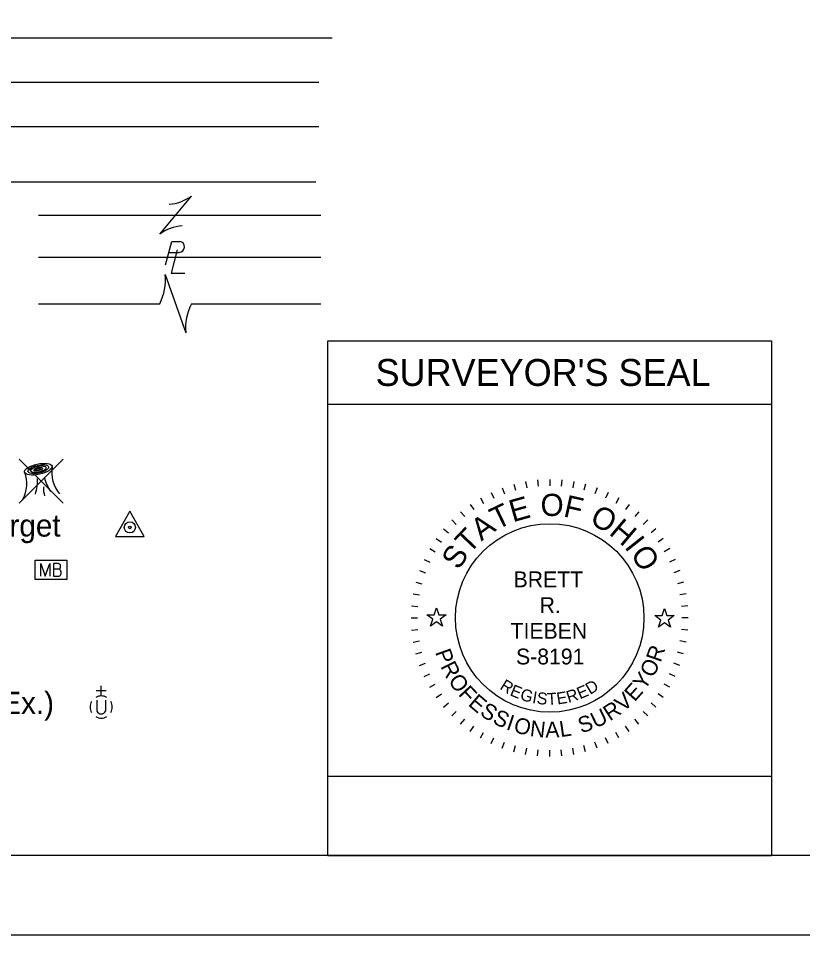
# Model space of a CAD drawing. Extents: x 0 to 34, y 0 to 22.
# Drawn here: x 12.19 to 17.15, y 0 to 5.79 of the extents above; entities that cross this region are included whole.
import ezdxf

# ---------------------------------------------------------------- set-up
doc = ezdxf.new("R2010")
doc.units = 0
for name, color, linetype in [('SH_Border', 7, 'Continuous'), ('SH_Cut_Line', 7, 'Continuous'), ('SH_Data', 7, 'Continuous'), ('SH_Text', 7, 'Continuous')]:
    doc.layers.add(name, color=color, linetype=linetype)

msp = doc.modelspace()

# ---------------------------------------------------------------- linework, layer by layer
at = {"layer": 'SH_Border'}
msp.add_lwpolyline([(1.5, 21.5), (33.5, 21.5), (33.5, 0.5), (1.5, 0.5)], close=True, dxfattribs=at)
at = {"layer": 'SH_Cut_Line'}
msp.add_lwpolyline([(0, 0), (34, 0), (34, 22), (0, 22)], close=True, dxfattribs=at)
at = {"layer": 'SH_Data'}
for p, q in [((14.1482, 0.5), (14.1482, 3.75)), ((14.1482, 3.75), (16.9482, 3.75)), ((16.9482, 3.75), (16.9482, 0.5)), ((14.1482, 3.35), (16.9482, 3.35)), ((15.3217, 2.8452), (15.3321, 2.8065)), ((15.3962, 2.8617), (15.4032, 2.8223)), ((15.4719, 2.8717), (15.4754, 2.8318)), ((15.5482, 2.875), (15.5482, 2.835)), ((15.6244, 2.8717), (15.6209, 2.8318)), ((15.7001, 2.8617), (15.6932, 2.8223)), ((15.7746, 2.8452), (15.7643, 2.8065)), ((15.1784, 2.793), (15.1953, 2.7568)), ((15.2489, 2.8222), (15.2626, 2.7846)), ((15.8474, 2.8222), (15.8338, 2.7846)), ((15.918, 2.793), (15.9011, 2.7568)), ((15.1107, 2.7578), (15.1307, 2.7231)), ((15.9857, 2.7578), (15.9657, 2.7231)), ((14.9857, 2.6703), (15.0114, 2.6396)), ((15.0463, 2.7168), (15.0692, 2.684)), ((16.05, 2.7168), (16.0271, 2.684)), ((16.1106, 2.6703), (16.0849, 2.6396)), ((14.9294, 2.6187), (14.9577, 2.5904)), ((16.1669, 2.6187), (16.1386, 2.5904)), ((14.8779, 2.5624), (14.9085, 2.5367)), ((16.2185, 2.5624), (16.1878, 2.5367)), ((14.8314, 2.5019), (14.8642, 2.4789)), ((16.2649, 2.5019), (16.2322, 2.4789)), ((14.7904, 2.4375), (14.825, 2.4175)), ((16.3059, 2.4375), (16.2713, 2.4175)), ((14.7551, 2.3698), (14.7914, 2.3529)), ((16.3412, 2.3698), (16.3049, 2.3529)), ((14.7259, 2.2993), (14.7635, 2.2856)), ((16.3704, 2.2993), (16.3328, 2.2856)), ((14.703, 2.2265), (14.7416, 2.2161)), ((16.3933, 2.2265), (16.3547, 2.2161)), ((14.6865, 2.1519), (14.7258, 2.145)), ((16.4099, 2.1519), (16.3705, 2.145)), ((14.6765, 2.0763), (14.7163, 2.0728)), ((16.4198, 2.0763), (16.38, 2.0728)), ((14.6732, 2), (14.7132, 2)), ((16.4232, 2), (16.3832, 2)), ((14.6765, 1.9237), (14.7163, 1.9272)), ((16.4198, 1.9237), (16.38, 1.9272)), ((14.6865, 1.8481), (14.7258, 1.855)), ((16.4099, 1.8481), (16.3705, 1.855)), ((14.703, 1.7735), (14.7416, 1.7839)), ((16.3933, 1.7735), (16.3547, 1.7839)), ((14.7259, 1.7007), (14.7635, 1.7144)), ((16.3704, 1.7007), (16.3328, 1.7144)), ((14.7551, 1.6302), (14.7914, 1.6471)), ((16.3412, 1.6302), (16.3049, 1.6471)), ((14.7904, 1.5625), (14.825, 1.5825)), ((16.3059, 1.5625), (16.2713, 1.5825)), ((14.8314, 1.4981), (14.8642, 1.5211)), ((16.2649, 1.4981), (16.2322, 1.5211)), ((14.8779, 1.4376), (14.9085, 1.4633)), ((16.2185, 1.4376), (16.1878, 1.4633)), ((14.9294, 1.3813), (14.9577, 1.4096)), ((16.1669, 1.3813), (16.1386, 1.4096)), ((14.9857, 1.3297), (15.0114, 1.3604)), ((16.1106, 1.3297), (16.0849, 1.3604)), ((15.0463, 1.2832), (15.0692, 1.316)), ((15.1107, 1.2422), (15.1307, 1.2769)), ((15.9857, 1.2422), (15.9657, 1.2769)), ((16.05, 1.2832), (16.0271, 1.316)), ((15.1784, 1.207), (15.1953, 1.2432)), ((15.2489, 1.1778), (15.2626, 1.2154)), ((15.8474, 1.1778), (15.8338, 1.2154)), ((15.918, 1.207), (15.9011, 1.2432)), ((15.3217, 1.1548), (15.3321, 1.1935)), ((15.3962, 1.1383), (15.4032, 1.1777)), ((15.4719, 1.1283), (15.4754, 1.1682)), ((15.5482, 1.125), (15.5482, 1.165)), ((15.6244, 1.1283), (15.6209, 1.1682)), ((15.7001, 1.1383), (15.6932, 1.1777)), ((15.7746, 1.1548), (15.7643, 1.1935)), ((14.1482, 0.5), (16.9482, 0.5))]:
    msp.add_line(p, q, dxfattribs=at)
for points in [[(14.7718, 2.02), (14.8187, 2.02), (14.8332, 2.0645), (14.8477, 2.02), (14.8945, 2.02), (14.8567, 1.9924), (14.8711, 1.9478), (14.8332, 1.9754), (14.7952, 1.9478), (14.8097, 1.9924)], [(16.2109, 2.0146), (16.2578, 2.0146), (16.2723, 2.0591), (16.2868, 2.0146), (16.3336, 2.0146), (16.2958, 1.987), (16.3103, 1.9424), (16.2723, 1.97), (16.2343, 1.9424), (16.2488, 1.987)], [(14.1482, 0.5), (14.1482, 1), (16.9482, 1), (16.9482, 0.5)]]:
    msp.add_lwpolyline(points, close=True, dxfattribs=at)
msp.add_circle((15.5482, 2), 0.595, dxfattribs=at)
at = {"layer": 'SH_Text'}
for p, q in [((10.6907, 5.6637), (14.1741, 5.6637)), ((10.1904, 5.3837), (14.0904, 5.3837)), ((10.1904, 5.1037), (14.0904, 5.1037)), ((9.7227, 4.7537), (14.0727, 4.7537)), ((13.0859, 4.4237), (13.2859, 4.6637)), ((12.3204, 4.5437), (14.1027, 4.5437)), ((13.1859, 4.5437), (13.1859, 4.5437)), ((13.1436, 4.3087), (13.2084, 4.3087)), ((12.3204, 4.2791), (14.1027, 4.2791)), ((13.1837, 4.2775), (13.1837, 4.2775)), ((13.1209, 4.1679), (13.2509, 3.7997)), ((12.3204, 3.9837), (13.086, 3.9837)), ((13.1859, 3.9838), (13.1859, 3.9838)), ((13.2858, 3.9837), (14.1027, 3.9837)), ((12.1991, 3.0028), (12.4772, 2.7247)), ((12.4772, 3.0028), (12.1991, 2.7247)), ((12.3382, 2.8638), (12.3382, 2.8638)), ((12.3382, 2.8637), (12.3382, 2.8637)), ((12.3994, 2.3037), (12.3994, 2.3037)), ((12.7168, 1.5074), (12.7168, 1.5709)), ((12.7485, 1.5391), (12.6849, 1.5391)), ((12.6896, 1.4804), (12.6896, 1.4115)), ((12.7439, 1.4804), (12.7439, 1.4115)), ((12.7168, 1.4374), (12.7168, 1.4374))]:
    msp.add_line(p, q, dxfattribs=at)
for points in [[(13.1226, 4.2291), (13.1617, 4.3773), (13.2134, 4.3772)], [(13.197, 4.3255), (13.1574, 4.1777), (13.2448, 4.1777)], [(12.3346, 2.2637), (12.3346, 2.3437), (12.3636, 2.2637), (12.3913, 2.3437), (12.3913, 2.2637)], [(12.4505, 2.3072), (12.4537, 2.3104), (12.4556, 2.3123), (12.4568, 2.3141), (12.4575, 2.3154), (12.4587, 2.3179), (12.4594, 2.3198), (12.4606, 2.3242), (12.4606, 2.3261), (12.4606, 2.3286), (12.46, 2.3324), (12.4587, 2.3356), (12.4568, 2.3381), (12.4537, 2.3406), (12.4512, 2.3419), (12.4499, 2.3425), (12.4468, 2.3437), (12.4159, 2.3437), (12.4159, 2.2637), (12.4505, 2.2637), (12.4549, 2.2663), (12.4587, 2.2694), (12.4619, 2.2745), (12.4638, 2.2801), (12.4644, 2.2858), (12.4644, 2.2896), (12.4631, 2.2934), (12.4606, 2.299), (12.4575, 2.3028), (12.4505, 2.3072), (12.4159, 2.3072)]]:
    msp.add_lwpolyline(points, dxfattribs=at)
for points in [[(12.8076, 2.5137), (12.9876, 2.5137), (12.8976, 2.6747)], [(12.2994, 2.3648), (12.4994, 2.3648), (12.4994, 2.2427), (12.2994, 2.2427)]]:
    msp.add_lwpolyline(points, close=True, dxfattribs=at)
for radius in [0.035, 0.008]:
    msp.add_circle((12.8976, 2.5716), radius, dxfattribs=at)
for centre, radius, start, end in [((13.1278, 4.8787), 0.2668, 273.69448, 306.33701), ((13.244, 4.2088), 0.2668, 93.69448, 126.33701), ((13.2082, 4.3431), 0.0345, 270.47098, 81.3281), ((12.7889, 4.1355), 0.3335, 332.94224, 5.58476), ((13.5829, 3.8321), 0.3335, 152.94224, 185.58476), ((12.6185, 2.9208), 0.2146, 171.41061, 219.91939), ((12.0466, 2.8464), 0.2001, 331.53375, 20.92689), ((12.0623, 2.865), 0.2527, 340.79377, 3.54808), ((12.6636, 2.9666), 0.316, 194.9653, 212.12159), ((12.5334, 2.8237), 0.1819, 178.79264, 197.12241), ((12.7168, 1.4374), 0.07, 60.01836, 120.01574), ((12.7168, 1.4374), 0.07, 150.01836, 209.98164), ((12.7168, 1.4374), 0.07, 330.01836, 29.98164), ((12.7167, 1.4243), 0.03, 205.19243, 334.80757), ((12.7168, 1.4374), 0.07, 239.98426, 299.98164)]:
    msp.add_arc(centre, radius, start, end, dxfattribs=at)
for major_axis in [(0.0868, 0.0187), (0.0651, 0.0141), (0.0488, 0.0105), (0.0275, 0.0059), (0.0154, 0.0033)]:
    msp.add_ellipse((12.3194, 2.9393), major_axis=major_axis, ratio=0.36865, dxfattribs=at)

# ---------------------------------------------------------------- texts
at = {"layer": 'SH_Data'}
for s, height, p in [("SURVEYOR'S SEAL", 0.17, (14.4488, 3.465)), ('BRETT', 0.1, (15.3205, 2.1938)), ('R.', 0.1, (15.4844, 2.0312)), ('TIEBEN', 0.1, (15.3015, 1.8687)), ('S-8191', 0.1, (15.3358, 1.7063))]:
    msp.add_text(s, height=height, dxfattribs=at).set_placement(p)
for s, height, rotation, p in [('O', 0.14, 359.78119, (15.4902, 2.6442)), ('T', 0.14, 25.71674, (15.2142, 2.554)), ('E', 0.14, 15.75706, (15.3151, 2.6034)), ('F', 0.14, 347.43619, (15.6292, 2.6417)), ('O', 0.14, 332.25863, (15.7944, 2.5981)), ('A', 0.14, 36.47472, (15.1167, 2.4819)), ('H', 0.14, 319.91363, (15.9166, 2.5316)), ('T', 0.14, 46.4344, (15.0399, 2.4)), ('I', 0.14, 308.36695, (16.0156, 2.4471)), ('S', 0.14, 57.19238, (14.9741, 2.2981)), ('O', 0.14, 303.14906, (16.0543, 2.4028)), ('P', 0.1, 289.74314, (14.8236, 1.7839)), ('R', 0.1, 70.983, (16.2485, 1.7149)), ('R', 0.1, 296.98022, (14.8566, 1.6943)), ('O', 0.1, 62.74284, (16.2004, 1.6174)), ('O', 0.1, 304.7158, (14.904, 1.604)), ('Y', 0.1, 55.50576, (16.147, 1.5383)), ('F', 0.1, 312.95596, (14.9674, 1.5158)), ('R', 0.075, 327.82385, (15.2283, 1.554)), ('E', 0.075, 337.77772, (15.2921, 1.5128)), ('E', 0.075, 23.30524, (15.7391, 1.4856)), ('D', 0.075, 31.46601, (15.8032, 1.5136)), ('E', 0.1, 48.26868, (16.0841, 1.4666)), ('E', 0.1, 319.68845, (15.0282, 1.451)), ('G', 0.075, 344.27273, (15.3564, 1.4848)), ('I', 0.075, 350.64643, (15.435, 1.4634)), ('S', 0.075, 353.78581, (15.4636, 1.4581)), ('T', 0.075, 3.00609, (15.5333, 1.4505)), ('E', 0.075, 8.98261, (15.5974, 1.453)), ('R', 0.075, 17.68363, (15.6669, 1.4627)), ('V', 0.1, 41.03161, (16.0126, 1.4033)), ('S', 0.1, 326.92553, (15.1015, 1.3899)), ('R', 0.1, 33.29603, (15.9281, 1.3462)), ('S', 0.1, 334.16261, (15.1819, 1.3385)), ('U', 0.1, 25.56045, (15.8366, 1.301)), ('I', 0.1, 341.39968, (15.2681, 1.2976)), ('O', 0.1, 345.13508, (15.3145, 1.2809)), ('N', 0.1, 353.37524, (15.42, 1.2548)), ('A', 0.1, 1.11082, (15.5214, 1.2443)), ('L', 0.1, 8.3479, (15.6168, 1.247)), ('S', 0.1, 18.32337, (15.7463, 1.2703))]:
    msp.add_text(s, height=height, rotation=rotation, dxfattribs=at).set_placement(p)
at = {"layer": 'SH_Text'}
for s, p in [('Wetland (Pr)         , Grass (Pr)            , Aerial Target    ', (8.1741, 2.5137)), ('Water Valve (Ex)         , Utility Valve Unknown (Ex.)', (8.1741, 1.3937))]:
    msp.add_text(s, height=0.14, dxfattribs=at).set_placement(p)

doc.saveas('drawing.dxf')
